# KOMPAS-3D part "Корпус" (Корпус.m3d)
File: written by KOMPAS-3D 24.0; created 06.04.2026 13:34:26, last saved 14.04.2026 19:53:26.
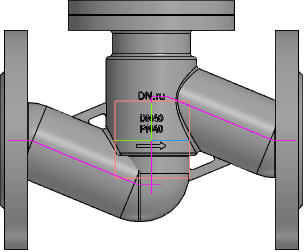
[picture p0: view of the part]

Document properties: Автор: R2D2; Полное имя файла: E:\Работа\Зайцев\VSO3131M-F-S Клапан запорный DN.ru Ду15-100 Ру40\DN40\исходные материалы\Корпус.m3d

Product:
- Body: Труба / Нестандартная труба / L = 100.7 мм  | qty 1
    Материал: Нестандартная труба (density 7856 kg/m3)
    Масса: 9.06151
    Раздел спецификации: Детали
    Примечание: 1,55 кг
    additional columns: Pipeline; 0.05; 0; 0; 0.002; 0.1007; true; 0.04
- Body: Труба / Нестандартная труба / L = 126.7 мм  | qty 1
    Материал: Нестандартная труба (density 7856 kg/m3)
    Масса: 9.06151
    Раздел спецификации: Детали
    Примечание: 1,95 кг
    additional columns: Pipeline; 0.05; 0; 0; 0.002; 0.12669; true; 0.04
- Body: Тело 4  | qty 1
    Материал: Нестандартная труба (density 7856 kg/m3)
    Масса: 9.06151
- Body: Тело 5  | qty 1
    Материал: Нестандартная труба (density 7856 kg/m3)
    Масса: 9.06151
- Body: Тело 8  | qty 1
    Материал: Нестандартная труба (density 7856 kg/m3)
    Масса: 9.06151
- Body: Тело 9  | qty 1
    Материал: Нестандартная труба (density 7856 kg/m3)
    Масса: 9.06151
- Part/product: Корпус
    Масса: 6.9

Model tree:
1. Труба
2. Труба:1  (labels: {F703FF30-5BE6-4673-A7F1-8EDA1BE1E2D1}; SHAPEOBJECT3D_ATTR_BUTT; SHAPEOBJECT3D_ATTR_VALID; SHAPEOBJECT3D_ATTR_BUTT_AREA)
     PIPE_R = 7
3. Труба:2  (labels: {F703FF30-5BE6-4673-A7F1-8EDA1BE1E2D1}; SHAPEOBJECT3D_ATTR_BUTT; SHAPEOBJECT3D_ATTR_VALID; SHAPEOBJECT3D_ATTR_BUTT_AREA)
     PIPE_R = 7
4. Колонна
5. Элемент выдавливания:1
     Смещение 1 = -1; Смещение 2 = -5
6. Скругление:17  (with: Ребро.Элемент выдавливания:1)
     Радиус = 1
7. Скругление:18  (with: Ребро.Элемент выдавливания:1)
8. Скругление:24  (with: Ребро.Элемент выдавливания:1)
     Радиус = 1.5
9. Элемент выдавливания:2
     Расстояние 1 = 6
10. Скругление:19  (with: Ребро.Элемент выдавливания:2)
     Радиус = 2
11. Эскиз:4  (with: Грань.Элемент выдавливания:1)
12. Элемент выдавливания:3
     Расстояние 1 = 17.5
13. Скругление:21  (with: Ребро.Элемент выдавливания:3)
14. ОТЛИВКА
15. Скругление:6  (with: Грань.Элемент выдавливания:1)
     Радиус = 2
16. Элемент выдавливания:6  (with: Грань.Элемент выдавливания:1)
     Смещение 1 = 4
17. ЛЕЙБЛ
18. Элемент выдавливания:7  (with: Грань.Элемент выдавливания:1)
     Расстояние 1 = 30.9953; Смещение 1 = 1
19. Фланец верх  (with: Ребро.Элемент выдавливания:3)
20. Элемент вращения:2
     Угол 1 = 360
21. Эскиз:12  (with: Грань.Элемент вращения:2)
22. Элемент выдавливания:9  (with: Грань.Элемент вращения:2)
     Расстояние 2 = 20
23. Массив по концентрической сетке:1  (with: Элемент выдавливания:9, Эскиз:12, Грань.Элемент вращения:2)  (4 pattern instances)
     Шаг 2 = 360
24. Фланец
25. Элемент вращения:1
     Угол 1 = 360
26. отвертие во фланце  (with: Грань.Элемент вращения:1)
27. Элемент выдавливания:8
28. Массив по концентрической сетке:2  (with: Элемент выдавливания:8, Эскиз:10, Грань.Элемент вращения:1)  (4 pattern instances)
     Шаг 2 = 360
29. Зеркальный массив:1
30. Экземпляр ( 1 )
31. Экземпляр ( 2 )  (with: Элемент вращения:1, Массив по концентрической сетке:2, Экземпляр ( 1 ), Элемент выдавливания:8)
32. Экземпляр ( 3 )  (with: Элемент выдавливания:8)
33. Экземпляр ( 4 )  (with: Элемент выдавливания:8)
34. Скругление:25  (with: Ребро.Элемент вращения:2)
     Радиус = 2

Expressions: DS/2+3; D1/2; DN/2; D/2; DS-v977*4; LL/2; D1-v1234*2
Referenced files in C:\Program Files\ASCON\KOMPAS-3D v24\Libs\Pipeline\: StylesTemplate.a3d, TemplateHPH, InsulationStylesTemplate.a3d, Insulation
Referenced files in C:\Program Files\ASCON\KOMPAS-3D v24\Templates\: Констр. чертеж А3 гориз. перв. лист.cdt
Referenced files in E:\Работа\Зайцев\VSO3131M-F-S Клапан запорный DN.ru Ду15-100 Ру40\DN20\исходные материалы\: 
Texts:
  Отводы ГОСТ 17375-2001
  Констр. чертеж А3 гориз. перв. лист.cdt
  GOST 26.020 Pr3
  var3D
  GOST 2.304 type A
  смещение колонны вниз
  LL-10
  DN+10
  Труба / Нестандартная труба / L = %s мм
